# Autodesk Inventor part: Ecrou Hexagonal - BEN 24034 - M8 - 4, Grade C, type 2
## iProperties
Created: 2002-04
Part Number: Ecrou Hexagonal - BEN 24034 - M8 - 4, Grade C, type 2
Material: Par défaut
Catalog Web Link: www.traceparts.com
Description: Ecrou Hexagonal - BEN 24034 - M8 - 4, Grade C, type 2
Document SubType Name: Modélisation
Designer: Maison
Control State: 0
Master: False
Checked Out: False
Shininess: 20.0
Length Units: 11269
Angle Units: 11279
Time Units: 11290
Mass Units: 11283
Length Display Precision: 3
Angle Display Precision: 2
Density: 0.0
Volumn: 0.0
Area: 0.0
PropertySet Name: Model Information
Author: Maison
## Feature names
1. Base1
